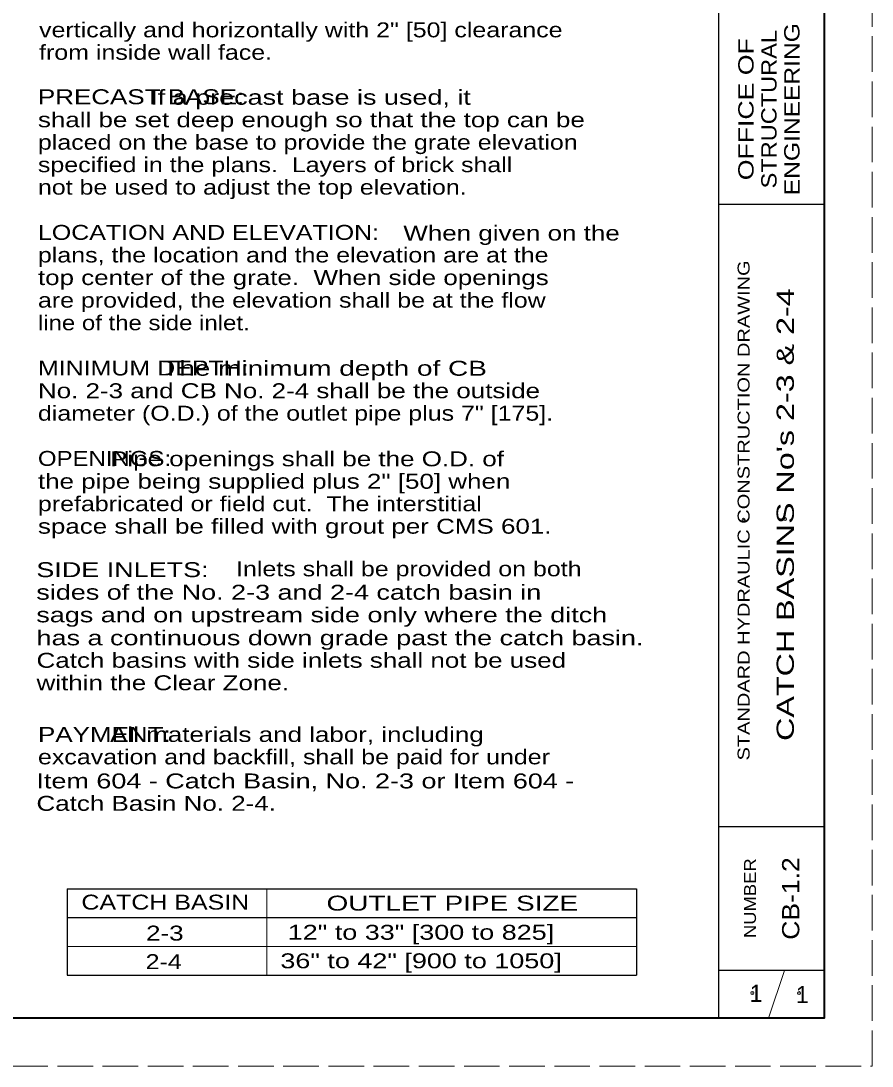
# Model space of a CAD drawing. Extents: x 1083.1 to 1117.1, y 697.4 to 719.4.
# Drawn here: x 1108.23 to 1117.13, y 697.35 to 708.27 of the extents above; entities that cross this region are included whole.
import ezdxf
from ezdxf.enums import TextEntityAlignment as Align

# ---------------------------------------------------------------- set-up
doc = ezdxf.new("R2010")
doc.units = 0
doc.header["$LTSCALE"] = 0.062
doc.header["$PDMODE"] = 32
doc.header["$PDSIZE"] = 0.031
doc.linetypes.add('LONG_DASHED', pattern=[7.5, 6, -1.5])
doc.layers.add('1', color=7, linetype='Continuous', lineweight=13)

msp = doc.modelspace()

# ---------------------------------------------------------------- linework, layer by layer
at = {"layer": '1', "lineweight": 25}
for p, q in [((1115.52642, 697.85408), (1115.52642, 718.85408)), ((1116.62642, 718.85408), (1116.62642, 697.85408)), ((1116.62642, 706.35408), (1115.52642, 706.35408)), ((1116.62642, 699.85408), (1115.52642, 699.85408)), ((1108.71467, 699.2045), (1114.66442, 699.2045)), ((1108.71467, 699.2045), (1108.71467, 698.30458)), ((1114.66442, 699.2045), (1114.66442, 698.30458)), ((1108.71467, 698.9045), (1114.66442, 698.9045)), ((1108.71467, 698.30458), (1114.66442, 698.30458)), ((1116.62642, 698.35408), (1115.52642, 698.35408))]:
    msp.add_line(p, q, dxfattribs=at)
at = {"layer": '1'}
for p, q in [((1110.8015, 699.2045), (1110.8015, 698.30458)), ((1108.71467, 698.60458), (1114.66442, 698.60458)), ((1116.04308, 697.85408), (1116.20975, 698.35408))]:
    msp.add_line(p, q, dxfattribs=at)
at = {"layer": '1', "linetype": 'LONG_DASHED'}
msp.add_lwpolyline([(1083.12642, 697.35408), (1117.12642, 697.35408), (1117.12642, 719.35408), (1083.12642, 719.35408)], close=True, dxfattribs=at)
at = {"layer": '1', "lineweight": 25}
msp.add_lwpolyline([(1116.62642, 697.85408), (1085.12642, 697.85408), (1085.12642, 718.85408)], dxfattribs=at)
at = {"layer": '1', "lineweight": 40}
msp.add_lwpolyline([(1085.12642, 718.85408), (1116.62642, 718.85408), (1116.62642, 697.85408), (1085.12642, 697.85408)], close=True, dxfattribs=at)
msp.add_lwpolyline([(1085.12642, 718.85408), (1116.62642, 718.85408), (1116.62642, 697.85408), (1085.12642, 697.85408)], close=True, dxfattribs=at)
at = {"layer": '1'}
for p in [(1115.78383, 703.06008), (1116.21667, 703.06742), (1115.8745, 698.11783), (1116.36292, 698.11683)]:
    msp.add_point(p, dxfattribs=at)

# ---------------------------------------------------------------- texts
for s, width, p in [('vertically and horizontally with 2" [50] clearance', 1.25, (1108.42242, 708.0995)), ('from inside wall face.', 1.25, (1108.42242, 707.86483)), ('PRECAST BASE:', 1.3, (1108.41058, 707.40083)), ('               If a precast base is used, it', 1.35, (1108.41058, 707.39508)), ('shall be set deep enough so that the top can be', 1.3, (1108.41058, 707.16042)), ('placed on the base to provide the grate elevation', 1.25, (1108.41058, 706.92575)), ('specified in the plans.  Layers of brick shall', 1.25, (1108.41058, 706.69108)), ('not be used to adjust the top elevation.', 1.25, (1108.41058, 706.45642)), ('LOCATION AND ELEVATION:', 1.25, (1108.41058, 705.98417)), ('When given on the', 1.3, (1112.22842, 705.977)), ('plans, the location and the elevation are at the', 1.25, (1108.41058, 705.74808)), ('top center of the grate.  When side openings', 1.3, (1108.41058, 705.512)), ('are provided, the elevation shall be at the flow', 1.25, (1108.41058, 705.27592)), ('line of the side inlet.', 1.2, (1108.41058, 705.03983)), ('MINIMUM DEPTH:', 1.25, (1108.41058, 704.56758)), ('                The minimum depth of CB', 1.4, (1108.41058, 704.56475)), ('No. 2-3 and CB No. 2-4 shall be the outside', 1.3, (1108.41058, 704.33008)), ('diameter (O.D.) of the outlet pipe plus 7" [175].', 1.25, (1108.41058, 704.09542)), ('OPENINGS:', 1.2, (1108.41058, 703.62317)), ('          Pipe openings shall be the O.D. of', 1.3, (1108.41058, 703.61892)), ('the pipe being supplied plus 2" [50] when', 1.3, (1108.41058, 703.38425)), ('prefabricated or field cut.  The interstitial', 1.25, (1108.41058, 703.14958)), ('space shall be filled with grout per CMS 601.', 1.3, (1108.41058, 702.91492)), ('SIDE INLETS:', 1.35, (1108.39392, 702.46125)), ('Inlets shall be provided on both', 1.25, (1110.48083, 702.46992)), ('sides of the No. 2-3 and 2-4 catch basin in ', 1.35, (1108.39392, 702.22525)), ('sags and on upstream side only where the ditch', 1.35, (1108.39392, 701.98925)), ('has a continuous down grade past the catch basin.  ', 1.35, (1108.39642, 701.749)), ('Catch basins with side inlets shall not be used ', 1.3, (1108.39642, 701.51433)), ('within the Clear Zone. ', 1.3, (1108.39642, 701.27967)), ('PAYMENT: ', 1.3, (1108.41117, 700.73992)), ('          All materials and labor, including', 1.3, (1108.41117, 700.73992)), ('excavation and backfill, shall be paid for under', 1.25, (1108.41117, 700.50592)), ('Item 604 - Catch Basin, No. 2-3 or Item 604 - ', 1.35, (1108.39525, 700.25442)), ('Catch Basin No. 2-4.', 1.3, (1108.39525, 700.02042)), ('CATCH BASIN', 1.25, (1108.86492, 698.9885)), ('OUTLET PIPE SIZE', 1.4, (1111.42592, 698.97808)), ('2-3', 1.3, (1109.5405, 698.66508)), ('12" to 33" [300 to 825]', 1.35, (1111.02083, 698.67358)), ('2-4', 1.25, (1109.53608, 698.36692)), ('36" to 42" [900 to 1050]', 1.35, (1110.94375, 698.37575))]:
    msp.add_text(s, height=0.156, dxfattribs=dict(at, width=width)).set_placement(p)
for s, height, width, p in [('ENGINEERING', 0.16, 1.2, (1116.36817, 707.34862)), ('OFFICE OF', 0.16, 1.3, (1115.88817, 707.34854)), ('STRUCTURAL', 0.16, 1.15, (1116.12817, 707.34854)), ('STANDARD HYDRAULIC CONSTRUCTION DRAWING', 0.125, 1.25, (1115.84633, 703.15812)), ("CATCH BASINS No's 2-3 & 2-4", 0.18, 1.4, (1116.309, 703.11421)), ('NUMBER', 0.125, 1.15, (1115.91342, 699.10817)), ('CB-1.2', 0.18, 1.15, (1116.36575, 699.10438))]:
    msp.add_text(s, height=height, rotation=90, dxfattribs=dict(at, width=width)).set_placement(p, align=Align.CENTER)
for p in [(1115.91427, 698.02417), (1116.3971, 698.01158)]:
    msp.add_text('1', height=0.18, dxfattribs=at).set_placement(p, align=Align.CENTER)

doc.saveas('drawing.dxf')
